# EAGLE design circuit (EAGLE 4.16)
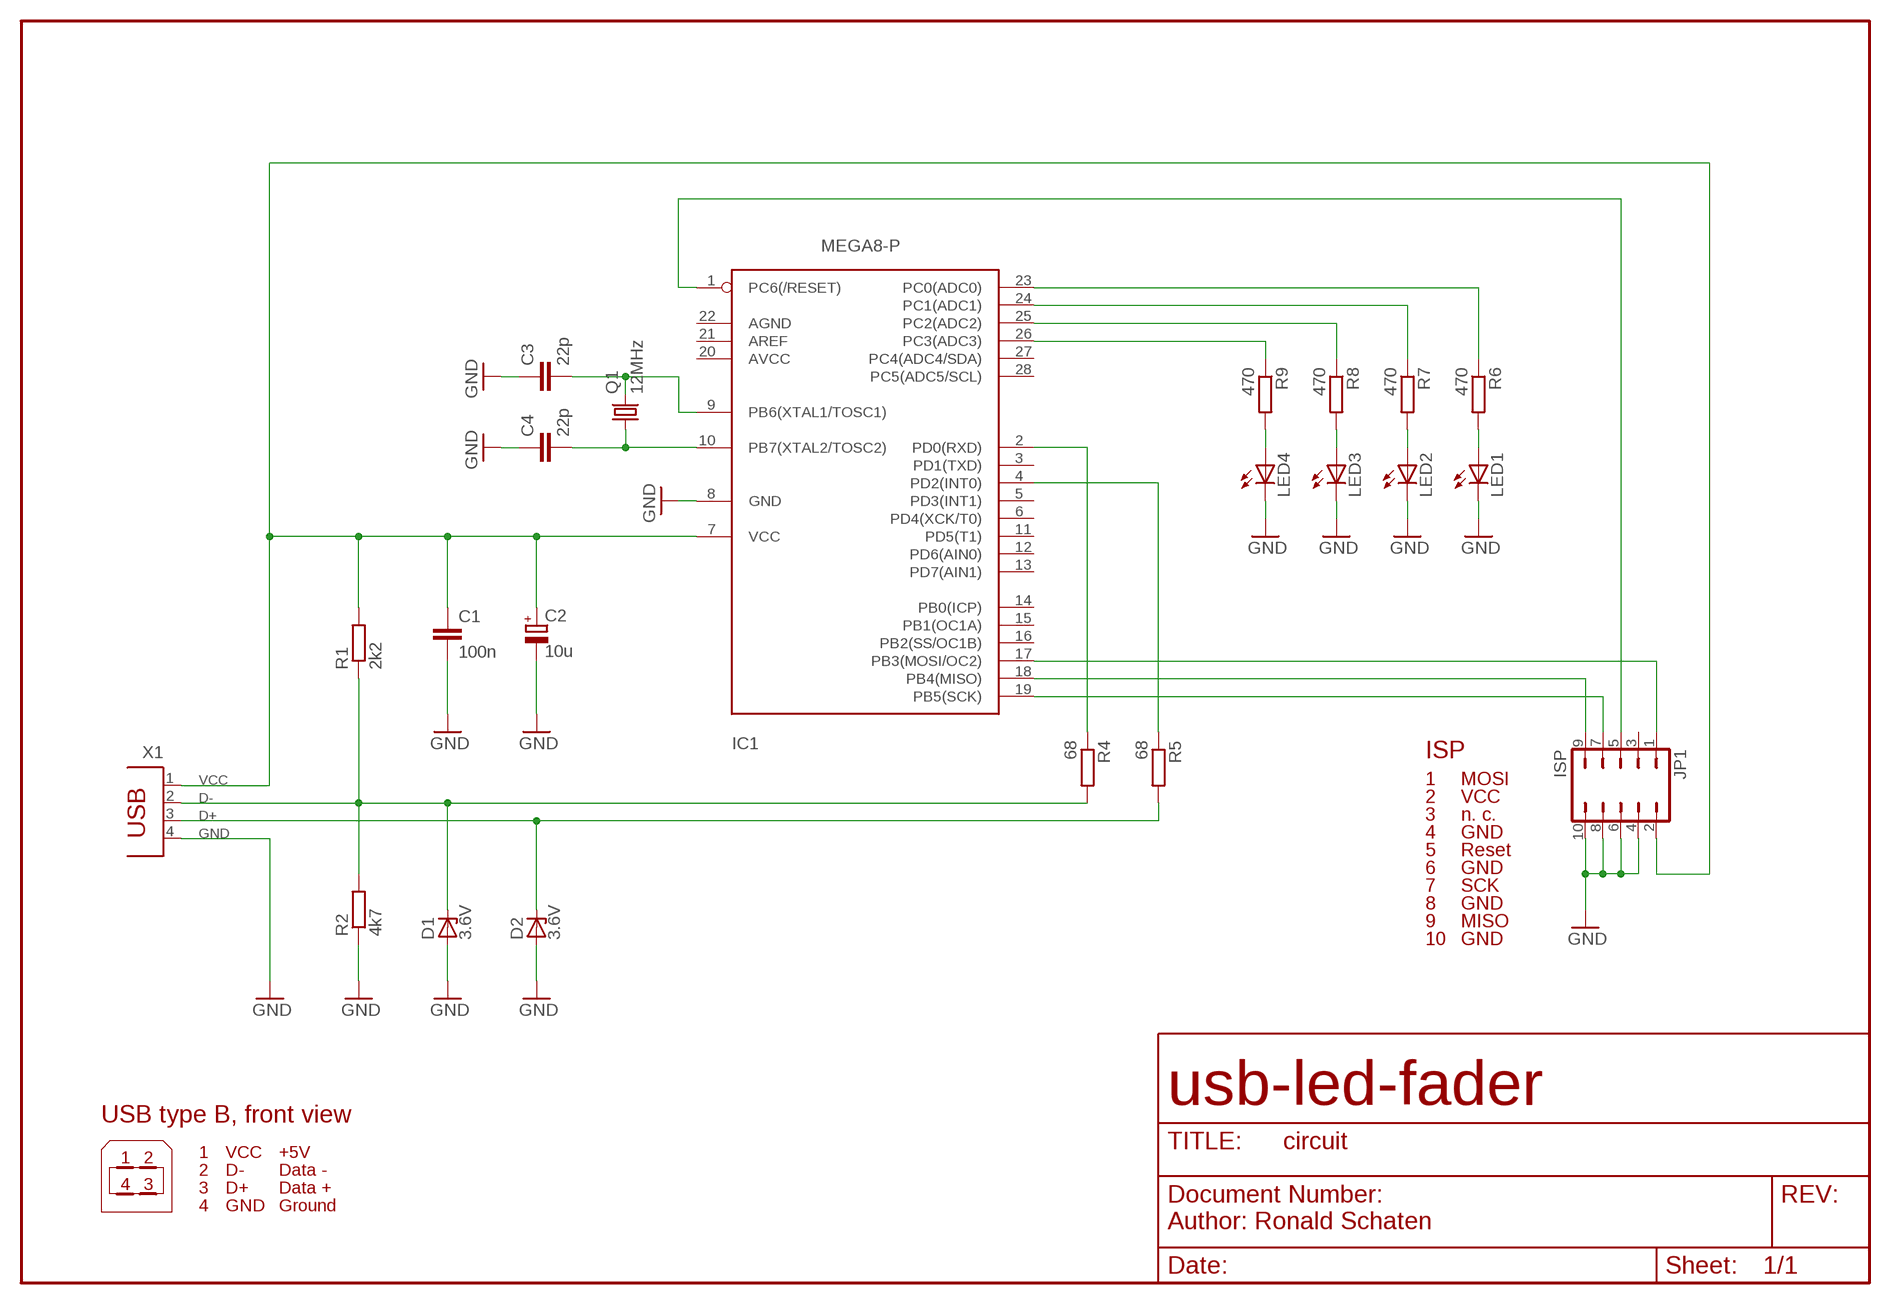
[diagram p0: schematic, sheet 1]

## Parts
C1  100n  C-EU025-024X044  [C025-024X044]
C2  10u  CPOL-EUE2.5-5  [E2,5-5]
C3  22p  C-EU025-024X044  [C025-024X044]
C4  22p  C-EU025-024X044  [C025-024X044]
D1  3.6V  ZENER-DIODEDO35Z10  [DO35Z10]
D2  3.6V  ZENER-DIODEDO35Z10  [DO35Z10]
IC1  MEGA8-P  [DIL28-3]
JP1  ISP  JP5Q  [JP5Q]
LED1  LED5MM  [LED5MM]
LED2  LED5MM  [LED5MM]
LED3  LED5MM  [LED5MM]
LED4  LED5MM  [LED5MM]
Q1  12MHz  CRYTALHC18U-V  [HC18U-V]
R1  2k2  R-EU_0207/10  [0207/10]
R2  4k7  R-EU_0207/10  [0207/10]
R4  68  R-EU_0207/10  [0207/10]
R5  68  R-EU_0207/10  [0207/10]
R6  470  R-EU_0207/10  [0207/10]
R7  470  R-EU_0207/10  [0207/10]
R8  470  R-EU_0207/10  [0207/10]
R9  470  R-EU_0207/10  [0207/10]
X1  PN61729  [PN61729]

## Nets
D+: D2.C R5.2 X1.3
D-: D1.C R1.1 R2.2 R4.2 X1.2
GND: C1.2 C2.- C3.1 C4.1 D1.A D2.A IC1.8(GND) JP1.4 JP1.6 JP1.8 JP1.10 LED1.K(C) LED2.K(C) LED3.K(C) LED4.K(C) R2.1 X1.4
N$1: IC1.2(PD0(RXD)) R4.1
N$2: C3.2 IC1.9(PB6(XTAL1/TOSC1)) Q1.2
N$7: C4.2 IC1.10(PB7(XTAL2/TOSC2)) Q1.1
N$9: IC1.4(PD2(INT0)) R5.1
N$11: IC1.17(PB3(MOSI/OC2)) JP1.1
N$12: IC1.1(PC6(/RESET)) JP1.5
N$13: IC1.26(PC3(ADC3)) R9.1
N$14: LED1.A R6.2
N$15: LED2.A R7.2
N$16: LED3.A R8.2
N$17: LED4.A R9.2
N$18: IC1.19(PB5(SCK)) JP1.7
N$19: IC1.25(PC2(ADC2)) R8.1
N$20: IC1.24(PC1(ADC1)) R7.1
N$21: IC1.23(PC0(ADC0)) R6.1
N$22: IC1.18(PB4(MISO)) JP1.9
VCC: C1.1 C2.+ IC1.7(VCC) JP1.2 R1.2 X1.1
Unconnected: IC1.3(PD1(TXD)) IC1.5(PD3(INT1)) IC1.6(PD4(XCK/T0)) IC1.11(PD5(T1)) IC1.12(PD6(AIN0)) IC1.13(PD7(AIN1)) IC1.14(PB0(ICP)) IC1.15(PB1(OC1A)) IC1.16(PB2(SS/OC1B)) IC1.20(AVCC) IC1.21(AREF) IC1.22(AGND) IC1.27(PC4(ADC4/SDA)) IC1.28(PC5(ADC5/SCL)) JP1.3

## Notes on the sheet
- ISP
- 1 | MOSI
- 2 | VCC
- 3 | n. c.
- 4 | GND
- 5 | Reset
- 6 | GND
- 7 | SCK
- 8 | GND
- 9 | MISO
- 10 | GND
- usb-led-fader
- USB type B, front view
- 1 | VCC | +5V
- 1 | 2
- 2 | D- | Data -
- 4 | 3 | 3 | D+ | Data +
- 4 | GND | Ground
- Author: Ronald Schaten

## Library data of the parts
C1 C3 C4 = rcl:C-EU: CAPACITOR, European symbol
C2 = rcl:CPOL-EU: POLARIZED CAPACITOR, European symbol
D1 D2 = diode:ZENER-DIODE: Z-Diode
IC1 = avr:MEGA8-P: MICROCONTROLLER 8 Kbytes FLASH 1 kbytes SRAM 512 bytes EEPROM USART 4-channel 10 bit ADC 2-channel 8 bit ADC
JP1 = jumper:JP5Q: JUMPER
LED1-LED4 = led:LED: LED
Q1 = crystal:CRYTAL: CRYSTAL
R1 R2 R4-R9 = rcl:R-EU_: RESISTOR, European symbol
X1 = con-berg:PN61729: BERG USB connector

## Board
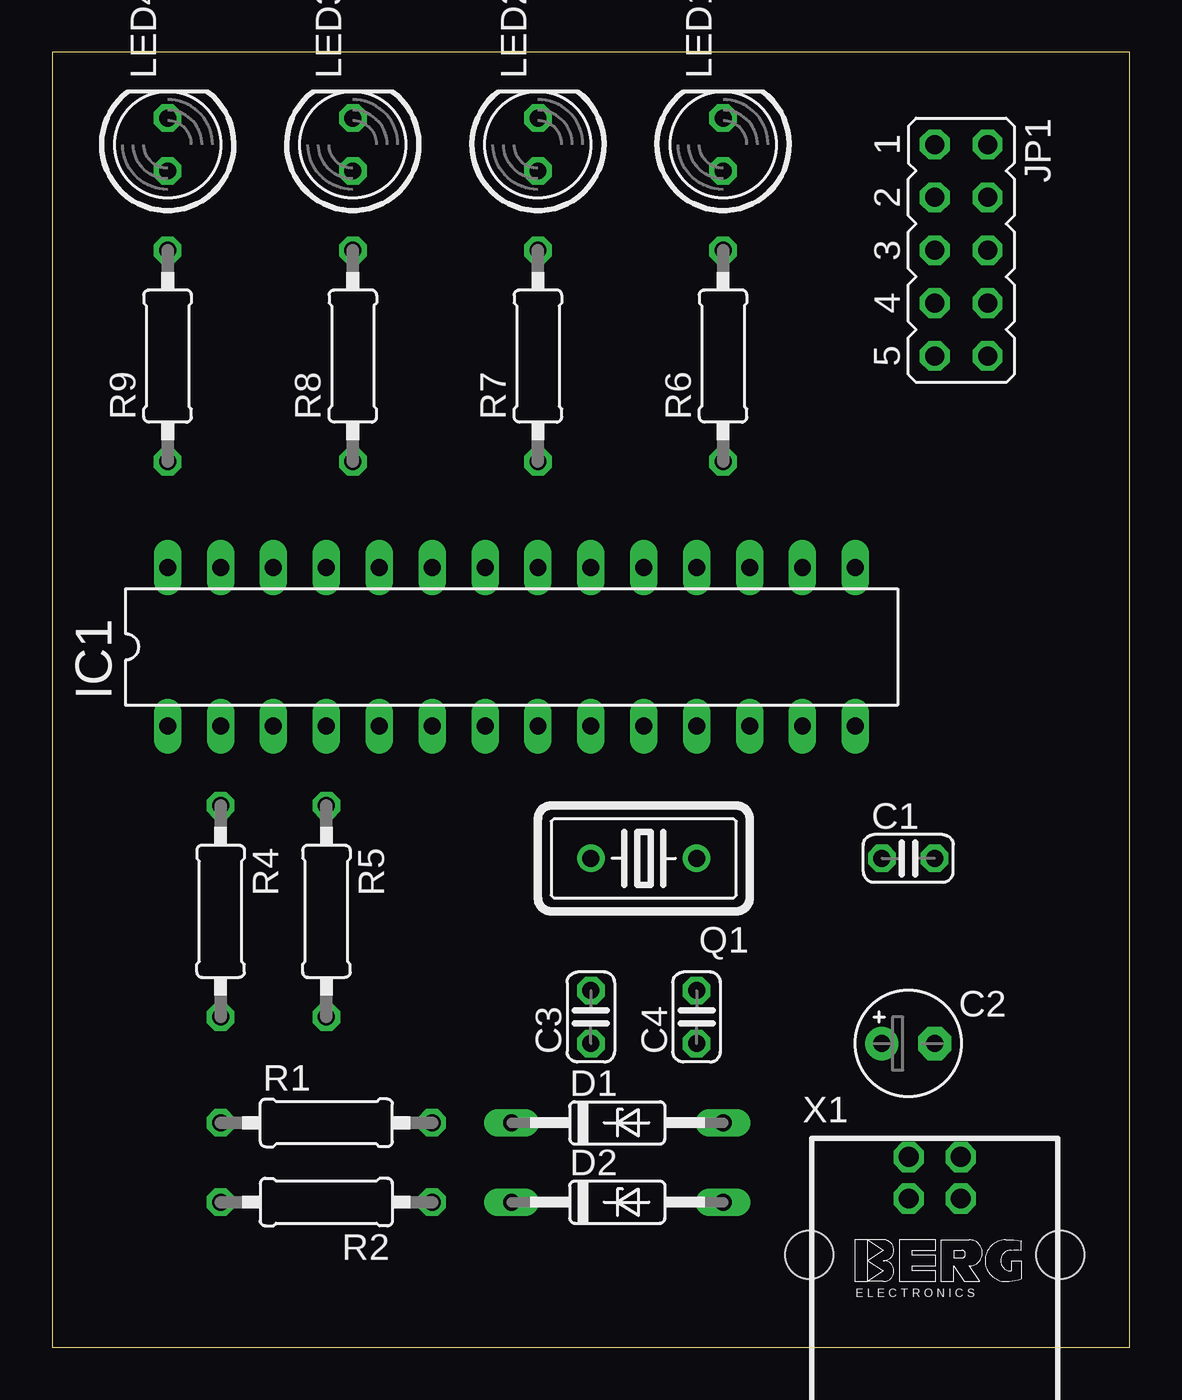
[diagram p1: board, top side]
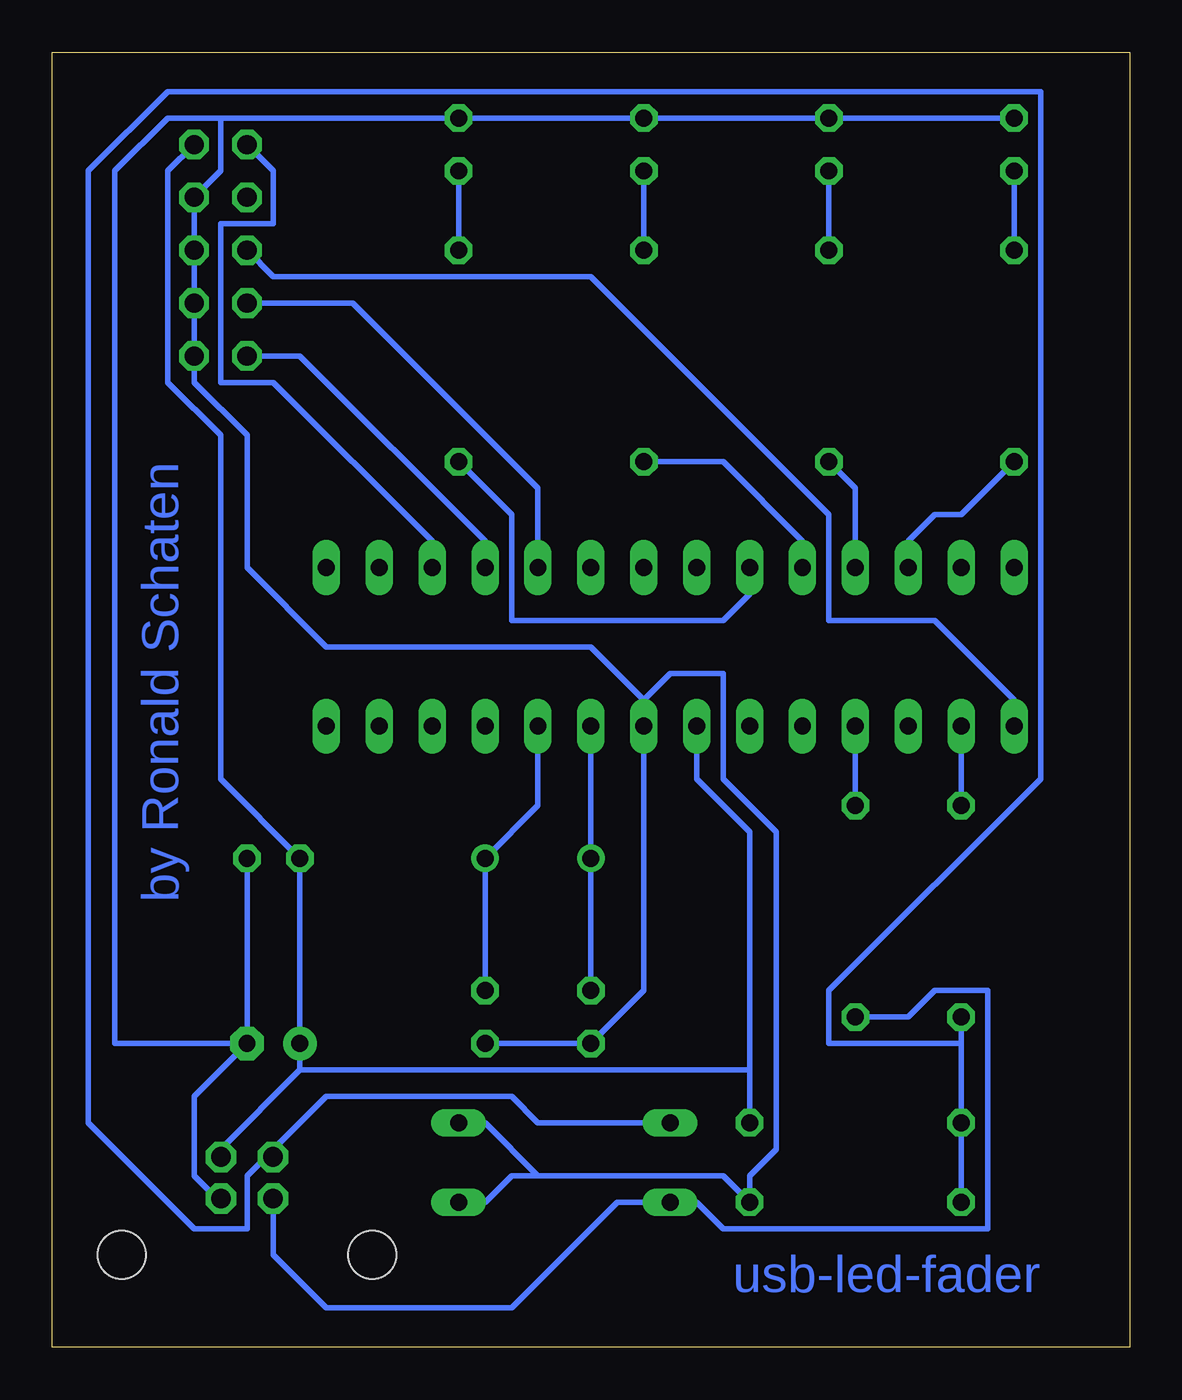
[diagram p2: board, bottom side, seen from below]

Size 51.74 x 62.22 mm. Coordinates in mm from the lower left corner, seen from the top.
Outline: 0,0 51.74,0 51.74,62.22 0,62.22 0,0
Copper layers (1*16): Top 0.035mm / dielectric 1.5mm / Bottom 0.035mm
Design rules "default": minimum track width 10mil, minimum drill 24mil, track to track 8mil, track to pad 8mil, pad to pad 8mil, via to via 8mil, smd to smd 8mil, copper to edge 40mil, drill to drill 8mil, minimum pad ring 10mil, minimum via ring 8mil, stop-mask expansion 4mil, vias tented up to drill 0mil, thermal gap 10mil

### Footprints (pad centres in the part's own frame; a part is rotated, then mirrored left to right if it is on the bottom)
C025-024X044 = drill 0.813 octagon: 1 -1.27,0; 2 1.27,0
E2,5-5 = drill 0.813 pad 1.6 round: + -1.27,0 | drill 0.813 pad 1.6 octagon: - 1.27,0
DO35Z10 = drill 0.813 long: A 5.08,0; C -5.08,0
DIL28-3 = drill 0.813 long: 1 -16.51,-3.81; 2 -13.97,-3.81; 3 -11.43,-3.81; 4 -8.89,-3.81; 5 -6.35,-3.81; 6 -3.81,-3.81; 7 -1.27,-3.81; 8 1.27,-3.81; 9 3.81,-3.81; 10 6.35,-3.81; 11 8.89,-3.81; 12 11.43,-3.81; 13 13.97,-3.81; 14 16.51,-3.81; 15 16.51,3.81; 16 13.97,3.81; 17 11.43,3.81; 18 8.89,3.81; 19 6.35,3.81; 20 3.81,3.81; 21 1.27,3.81; 22 -1.27,3.81; 23 -3.81,3.81; 24 -6.35,3.81; 25 -8.89,3.81; 26 -11.43,3.81; 27 -13.97,3.81; 28 -16.51,3.81
JP5Q = drill 0.914 octagon: 1 -5.08,-1.27; 2 -5.08,1.27; 3 -2.54,-1.27; 4 -2.54,1.27; 5 0,-1.27; 6 0,1.27; 7 2.54,-1.27; 8 2.54,1.27; 9 5.08,-1.27; 10 5.08,1.27
LED5MM = drill 0.813 octagon: A -1.27,0; K 1.27,0
HC18U-V = drill 0.813 round: 1 -2.54,0; 2 2.54,0
0207/10 = drill 0.813 octagon: 1 -5.08,0; 2 5.08,0
PN61729 = drill 0.95 octagon: 1 1.25,4.71; 2 -1.25,4.71; 3 -1.25,2.71; 4 1.25,2.71 | hole 2.3: -6.02,0; 6.02,0

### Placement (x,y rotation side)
C1  41.11,23.49 0 top
C2  41.11,14.6 0 top
C3  25.87,15.87 90 top
C4  30.95,15.87 90 top
D1  27.14,10.79 0 top
D2  27.14,6.98 0 top
IC1  22.06,33.65 0 top
JP1  43.65,52.7 270 top
LED1  32.22,57.78 90 top
LED2  23.33,57.78 90 top
LED3  14.44,57.78 90 top
LED4  5.55,57.78 90 top
Q1  28.41,23.49 180 top
R1  13.17,10.79 0 top
R2  13.17,6.98 180 top
R4  8.09,20.95 270 top
R5  13.17,20.95 270 top
R6  32.22,47.62 90 top
R7  23.33,47.62 90 top
R8  14.44,47.62 90 top
R9  5.55,47.62 90 top
X1  42.38,4.44 0 top

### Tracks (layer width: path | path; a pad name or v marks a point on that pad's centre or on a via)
D+
  Bottom 0.254: R5.2 10.63,15.87 9.36,17.14 6.82,17.14 6.82,5.71 19.52,5.71 20.79,6.98 D2.C 24.6,6.98 29.68,1.9 38.57,1.9 41.11,4.44 41.11,6.98 X1.3
D-
  Bottom 0.254: R2.2 R1.1 8.09,14.6 | 8.09,14.6 R4.2 | 41.11,9.52 38.57,12.06 29.68,12.06 28.41,10.79 D1.C | 8.09,14.6 14.44,14.6 14.44,17.14 4.28,27.3 4.28,60.32 46.19,60.32 50,56.51 50,10.79 44.92,5.71 42.38,5.71 42.38,8.25 41.11,9.52 | 41.11,9.52 X1.2
GND
  Bottom 0.254: C2.- C1.2 | C4.1 C3.1 23.33,17.14 IC1.8 23.33,31.11 | LED4.K LED3.K LED2.K LED1.K 43.65,59.05 | 43.65,59.05 43.65,56.51 JP1.4 JP1.6 JP1.8 JP1.10 44.92,46.35 42.38,43.81 42.38,37.46 38.57,33.65 25.87,33.65 23.33,31.11 | 28.41,8.25 29.68,8.25 30.95,6.98 D2.A | 28.41,8.25 19.52,8.25 R2.1 18.25,8.25 16.98,9.52 16.98,24.76 19.52,27.3 19.52,32.38 22.06,32.38 23.33,31.11 | 28.41,8.25 30.95,10.79 D1.A | C2.- 44.92,12.06 44.92,8.25 43.65,6.98 X1.4 | C2.- 48.73,14.6 48.73,56.51 46.19,59.05 43.65,59.05
N$1
  Bottom 0.254: R4.1 IC1.2
N$2
  Bottom 0.254: C3.2 Q1.2 IC1.9
N$7
  Bottom 0.254: C4.2 Q1.1 28.41,26.03 IC1.10
N$9
  Bottom 0.254: R5.1 IC1.4
N$11
  Bottom 0.254: JP1.1 41.11,56.51 41.11,53.97 43.65,53.97 43.65,46.35 41.11,46.35 33.49,38.73 IC1.17
N$12
  Bottom 0.254: JP1.5 41.11,51.43 25.87,51.43 14.44,40 14.44,34.92 9.36,34.92 5.55,31.11 IC1.1
N$13
  Bottom 0.254: R9.1 8.09,40 9.36,40 10.63,38.73 IC1.26
N$14
  Bottom 0.254: R6.2 LED1.A
N$15
  Bottom 0.254: R7.2 LED2.A
N$16
  Bottom 0.254: R8.2 LED3.A
N$17
  Bottom 0.254: R9.2 LED4.A
N$18
  Bottom 0.254: JP1.7 37.3,50.16 28.41,41.27 IC1.19
N$19
  Bottom 0.254: R8.1 13.17,41.27 IC1.25
N$20
  Bottom 0.254: R7.1 19.52,42.54 15.71,38.73 IC1.24
N$21
  Bottom 0.254: R6.1 29.68,40 29.68,34.92 19.52,34.92 18.25,36.19 IC1.23
N$22
  Bottom 0.254: JP1.9 39.84,47.62 30.95,38.73 IC1.18
VCC
  Bottom 0.254: 18.25,13.33 18.25,24.76 20.79,27.3 IC1.7 | R1.2 18.25,13.33 | JP1.2 46.19,56.51 46.19,46.35 43.65,43.81 43.65,27.3 C1.1 C2.+ 39.84,13.33 | 39.84,13.33 43.65,9.52 X1.1 | 18.25,13.33 39.84,13.33

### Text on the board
Bottom: by Ronald Schaten | usb-led-fader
